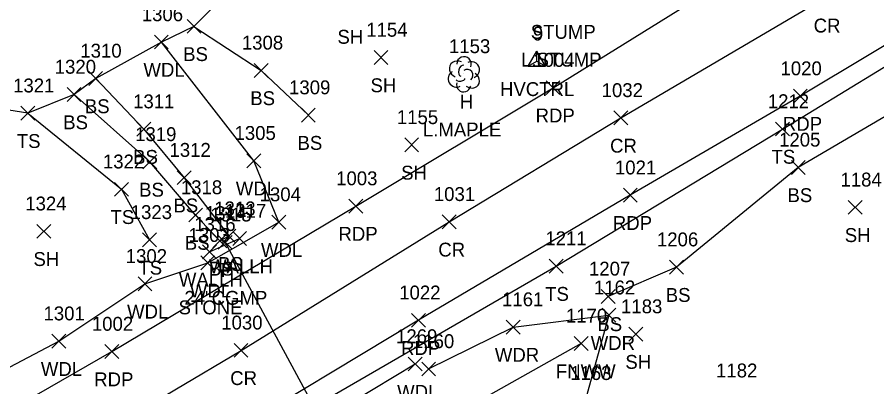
# Model space of a CAD drawing. Extents: x 1526508 to 1531550, y 369926 to 373082.
# Drawn here: x 1530712.1 to 1530836, y 370020.6 to 370073.8 of the extents above; entities that cross this region are included whole.
import ezdxf

# ---------------------------------------------------------------- set-up
doc = ezdxf.new("R2010")
doc.units = 0
for name, color, linetype in [('C_A', 7, 'Continuous'), ('C_I', 7, 'Continuous'), ('CPSM', 7, 'Continuous'), ('D_A', 7, 'Continuous'), ('D_C', 7, 'Continuous'), ('D_I', 7, 'Continuous'), ('D_TIC', 7, 'Continuous'), ('DCP', 7, 'Continuous'), ('DHW', 7, 'Continuous'), ('L_A', 7, 'Continuous'), ('L_C', 7, 'Continuous'), ('L_I', 7, 'Continuous'), ('L_TIC', 7, 'Continuous'), ('LAWA', 7, 'Continuous'), ('LELB', 7, 'Continuous'), ('LFNC', 7, 'Continuous'), ('LSOGP', 7, 'Continuous'), ('LTD', 7, 'Continuous'), ('P_A', 7, 'Continuous'), ('P_I', 7, 'Continuous'), ('P_TIC', 7, 'Continuous'), ('PET', 7, 'Continuous'), ('PRC', 7, 'Continuous')]:
    doc.layers.add(name, color=color, linetype=linetype)

msp = doc.modelspace()

# ---------------------------------------------------------------- linework, layer by layer
at = {"layer": 'CPSM'}
for p, q in [((1530785.76, 370066.72), (1530787.01, 370068.89)), ((1530788.26, 370066.72), (1530787.01, 370068.89)), ((1530787.01, 370067.44), (1530787.01, 370068.89)), ((1530785.76, 370066.72), (1530787.01, 370067.44)), ((1530787.01, 370067.44), (1530787.01, 370067.44)), ((1530787.01, 370067.44), (1530788.26, 370066.72)), ((1530785.76, 370066.72), (1530788.26, 370066.72))]:
    msp.add_line(p, q, dxfattribs=at)
at = {"layer": 'D_TIC'}
for points in [[(1530741.1, 370040.37), (1530743.1, 370042.37)], [(1530743.1, 370040.37), (1530741.1, 370042.37)], [(1530743.2, 370040.91), (1530745.2, 370042.91)], [(1530745.2, 370040.91), (1530743.2, 370042.91)], [(1530738.85, 370039), (1530740.85, 370041)], [(1530740.85, 370039), (1530738.85, 370041)]]:
    msp.add_lwpolyline(points, dxfattribs=at)
at = {"layer": 'DCP'}
msp.add_lwpolyline([(1530757.89, 370012.13), (1530742.1, 370041.37)], dxfattribs=at)
at = {"layer": 'DHW'}
msp.add_lwpolyline([(1530739.85, 370040), (1530744.2, 370041.91)], dxfattribs=at)
at = {"layer": 'L_TIC'}
for points in [[(1530736.62, 370071.48), (1530738.62, 370073.48)], [(1530738.62, 370071.48), (1530736.62, 370073.48)], [(1530731.92, 370069.22), (1530733.92, 370071.22)], [(1530733.92, 370069.22), (1530731.92, 370071.22)], [(1530763.57, 370066.99), (1530765.57, 370068.99)], [(1530765.57, 370066.99), (1530763.57, 370068.99)], [(1530746.29, 370065.13), (1530748.29, 370067.13)], [(1530748.29, 370065.13), (1530746.29, 370067.13)], [(1530722.46, 370063.97), (1530724.46, 370065.97)], [(1530724.46, 370063.97), (1530722.46, 370065.97)], [(1530719.34, 370061.66), (1530721.34, 370063.66)], [(1530721.34, 370061.66), (1530719.34, 370063.66)], [(1530712.68, 370058.96), (1530714.68, 370060.96)], [(1530714.68, 370058.96), (1530712.68, 370060.96)], [(1530753.1, 370058.69), (1530755.1, 370060.69)], [(1530755.1, 370058.69), (1530753.1, 370060.69)], [(1530729.41, 370056.67), (1530731.41, 370058.67)], [(1530731.41, 370056.67), (1530729.41, 370058.67)], [(1530821.42, 370056.69), (1530823.42, 370058.69)], [(1530823.42, 370056.69), (1530821.42, 370058.69)], [(1530767.98, 370054.4), (1530769.98, 370056.4)], [(1530769.98, 370054.4), (1530767.98, 370056.4)], [(1530730.27, 370051.95), (1530732.27, 370053.95)], [(1530732.27, 370051.95), (1530730.27, 370053.95)], [(1530745.24, 370052.12), (1530747.24, 370054.12)], [(1530747.24, 370052.12), (1530745.24, 370054.12)], [(1530823.69, 370051.16), (1530825.69, 370053.16)], [(1530825.69, 370051.16), (1530823.69, 370053.16)], [(1530735.22, 370049.68), (1530737.22, 370051.68)], [(1530737.22, 370049.68), (1530735.22, 370051.68)], [(1530726.19, 370048.01), (1530728.19, 370050.01)], [(1530728.19, 370048.01), (1530726.19, 370050.01)], [(1530831.89, 370045.41), (1530833.89, 370047.41)], [(1530833.89, 370045.41), (1530831.89, 370047.41)], [(1530736.86, 370044.3), (1530738.86, 370046.3)], [(1530738.86, 370044.3), (1530736.86, 370046.3)], [(1530748.85, 370043.28), (1530750.85, 370045.28)], [(1530750.85, 370043.28), (1530748.85, 370045.28)], [(1530715, 370041.96), (1530717, 370043.96)], [(1530717, 370041.96), (1530715, 370043.96)], [(1530730.2, 370040.72), (1530732.2, 370042.72)], [(1530732.2, 370040.72), (1530730.2, 370042.72)], [(1530740.33, 370040.58), (1530742.33, 370042.58)], [(1530742.33, 370040.58), (1530740.33, 370042.58)], [(1530741.67, 370041.25), (1530743.67, 370043.25)], [(1530743.67, 370041.25), (1530741.67, 370043.25)], [(1530738.6, 370037.43), (1530740.6, 370039.43)], [(1530740.6, 370037.43), (1530738.6, 370039.43)], [(1530788.81, 370036.94), (1530790.81, 370038.94)], [(1530790.81, 370036.94), (1530788.81, 370038.94)], [(1530806.15, 370036.79), (1530808.15, 370038.79)], [(1530808.15, 370036.79), (1530806.15, 370038.79)], [(1530729.56, 370034.39), (1530731.56, 370036.39)], [(1530731.56, 370034.39), (1530729.56, 370036.39)], [(1530796.3, 370032.58), (1530798.3, 370034.58)], [(1530798.3, 370032.58), (1530796.3, 370034.58)], [(1530796.41, 370029.87), (1530798.41, 370031.87)], [(1530798.41, 370029.87), (1530796.41, 370031.87)], [(1530782.61, 370028.16), (1530784.61, 370030.16)], [(1530784.61, 370028.16), (1530782.61, 370030.16)], [(1530800.28, 370027.15), (1530802.28, 370029.15)], [(1530802.28, 370027.15), (1530800.28, 370029.15)], [(1530717.14, 370026.13), (1530719.14, 370028.13)], [(1530719.14, 370026.13), (1530717.14, 370028.13)], [(1530792.41, 370025.8), (1530794.41, 370027.8)], [(1530794.41, 370025.8), (1530792.41, 370027.8)], [(1530768.48, 370022.84), (1530770.48, 370024.84)], [(1530770.48, 370022.84), (1530768.48, 370024.84)], [(1530770.43, 370022.13), (1530772.43, 370024.13)], [(1530772.43, 370022.13), (1530770.43, 370024.13)]]:
    msp.add_lwpolyline(points, dxfattribs=at)
at = {"layer": 'LAWA'}
for points in [[(1530657.29, 369993.12), (1530673.96, 370004), (1530696.13, 370015.56), (1530718.14, 370027.13), (1530730.56, 370035.39), (1530739.6, 370038.43), (1530749.85, 370044.28), (1530746.24, 370053.12), (1530732.92, 370070.22)], [(1530771.43, 370023.13), (1530783.61, 370029.16), (1530797.41, 370030.87), (1530793.99, 370018.54), (1530795.33, 370003.35), (1530805.3, 370002.27)], [(1530769.48, 370023.84), (1530754.36, 370014.7), (1530742.13, 370006.46), (1530732.58, 369998.98), (1530723.17, 369990.78), (1530701.39, 369977.34), (1530688.96, 369968.61), (1530674.75, 369962.19)]]:
    msp.add_lwpolyline(points, dxfattribs=at)
at = {"layer": 'LELB'}
for points in [[(1530685.88, 369975.28), (1530717.44, 369995.35), (1530750.55, 370015.24), (1530789.81, 370037.94), (1530822.42, 370057.69), (1530849.78, 370074.39), (1530878.97, 370089.95), (1530906.44, 370104.85), (1530934.55, 370113.45), (1530953.41, 370116.76)], [(1530737.62, 370072.48), (1530747.29, 370066.13), (1530754.1, 370059.69)], [(1530723.46, 370064.97), (1530730.41, 370057.67), (1530736.22, 370050.68), (1530742.67, 370042.25), (1530741.33, 370041.58), (1530737.86, 370045.3), (1530731.27, 370052.95), (1530720.34, 370062.66)], [(1530844.42, 370063.73), (1530824.69, 370052.16), (1530807.15, 370037.79), (1530797.3, 370033.58)], [(1530713.68, 370059.96), (1530727.19, 370049.01), (1530731.2, 370041.72)]]:
    msp.add_lwpolyline(points, dxfattribs=at)
at = {"layer": 'LFNC'}
msp.add_lwpolyline([(1530793.41, 370026.8), (1530770.35, 370013.82)], dxfattribs=at)
at = {"layer": 'LSOGP'}
msp.add_lwpolyline([(1530751.36, 370086.4), (1530737.62, 370072.48), (1530732.92, 370070.22), (1530723.46, 370064.97), (1530720.34, 370062.66), (1530713.68, 370059.96), (1530700.23, 370062.11)], dxfattribs=at)
at = {"layer": 'LTD'}
msp.add_line((1530776.49, 370065.62), (1530776.49, 370065.62), dxfattribs=at)
msp.add_line((1530776.49, 370065.62), (1530776.49, 370065.62), dxfattribs=at)
msp.add_arc((1530776.53, 370067.06), 1.05, 335.5272, 180.9563, dxfattribs=at)
for centre, major_axis, ratio, start_param, end_param in [((1530775.7, 370066.29), (1.21, -0.51), 0.895232, 1.570796, 4.712389), ((1530777.53, 370066.21), (-1.14, -0.48), 0.949671, 1.570796, 4.712389), ((1530775.4, 370064.91), (0.58, -1.04), 0.959034, 3.141593, 6.283185), ((1530776.28, 370066.08), (-0.208, -0.792), 0.645439, 3.141593, 6.283185), ((1530776.99, 370065.46), (-0.5, 0.667), 0.989748, 3.141593, 6.283185), ((1530776.03, 370064.87), (-0.625, -0.083), 0.423636, 0, 3.141593), ((1530777.49, 370064.79), (-1.09, 0.79), 0.841452, 1.570796, 4.712389), ((1530776.49, 370064.12), (0.26, 1.06), 0.942809, 1.570796, 4.712389)]:
    msp.add_ellipse(centre, major_axis=major_axis, ratio=ratio, start_param=start_param, end_param=end_param, dxfattribs=at)
at = {"layer": 'P_TIC'}
for points in [[(1530788.35, 370062.64), (1530790.35, 370064.64)], [(1530790.35, 370062.64), (1530788.35, 370064.64)], [(1530823.98, 370061.43), (1530825.98, 370063.43)], [(1530825.98, 370061.43), (1530823.98, 370063.43)], [(1530798.13, 370058.29), (1530800.13, 370060.29)], [(1530800.13, 370058.29), (1530798.13, 370060.29)], [(1530799.48, 370047.15), (1530801.48, 370049.15)], [(1530801.48, 370047.15), (1530799.48, 370049.15)], [(1530759.95, 370045.59), (1530761.95, 370047.59)], [(1530761.95, 370045.59), (1530759.95, 370047.59)], [(1530773.39, 370043.32), (1530775.39, 370045.32)], [(1530775.39, 370043.32), (1530773.39, 370045.32)], [(1530768.96, 370029.14), (1530770.96, 370031.14)], [(1530770.96, 370029.14), (1530768.96, 370031.14)], [(1530724.77, 370024.63), (1530726.77, 370026.63)], [(1530726.77, 370024.63), (1530724.77, 370026.63)], [(1530743.4, 370024.81), (1530745.4, 370026.81)], [(1530745.4, 370024.81), (1530743.4, 370026.81)]]:
    msp.add_lwpolyline(points, dxfattribs=at)
at = {"layer": 'PET'}
for points in [[(1530659.86, 369987.59), (1530689.68, 370004.88), (1530725.77, 370025.63), (1530760.95, 370046.59), (1530789.35, 370063.64), (1530821.52, 370083.59), (1530847.47, 370098.66), (1530877.57, 370115.25), (1530907.84, 370128.26), (1530938.81, 370136.76), (1530967.77, 370140.97), (1531005.44, 370146.08), (1531034.99, 370150.93)], [(1531038.44, 370130.38), (1531006.6, 370125.67), (1530965.47, 370120.56), (1530935.63, 370115.81), (1530906.91, 370106.24), (1530877.46, 370092.89), (1530855.5, 370080.74), (1530824.98, 370062.43), (1530800.48, 370048.15), (1530769.96, 370030.14), (1530741.1, 370012.79), (1530710.76, 369994.53), (1530684.03, 369978.66), (1530669.6, 369970.09)]]:
    msp.add_lwpolyline(points, dxfattribs=at)
at = {"layer": 'PRC'}
msp.add_lwpolyline([(1530664.43, 369978.53), (1530688.65, 369992.9), (1530715.76, 370008.79), (1530744.4, 370025.81), (1530774.39, 370044.32), (1530799.13, 370059.29), (1530828.47, 370076.59), (1530863.72, 370096.73), (1530899.64, 370113.89), (1530935.78, 370125.96), (1530974.77, 370132.27), (1531009.67, 370136.56), (1531036.22, 370140.48)], dxfattribs=at)

# ---------------------------------------------------------------- texts
at = {"layer": 'C_A'}
msp.add_text('HVCTRL', height=2, dxfattribs=at).set_placement((1530781.71, 370062.44))
at = {"layer": 'C_I'}
msp.add_text('9', height=2, dxfattribs=at).set_placement((1530786.44, 370070.44))
at = {"layer": 'D_A'}
for s, p in [('WALLH', (1530739.79, 370036.91)), ('P', (1530741.48, 370036.37)), ('WALLH', (1530735.44, 370035))]:
    msp.add_text(s, height=2, dxfattribs=at).set_placement(p)
at = {"layer": 'D_C'}
for s, p in [('24"CGMP', (1530736.24, 370032.37)), ('STONE', (1530735.4, 370031))]:
    msp.add_text(s, height=2, dxfattribs=at).set_placement(p)
at = {"layer": 'D_I'}
for s, p in [('1315', (1530739.98, 370044.37)), ('1317', (1530742.08, 370044.91)), ('1316', (1530737.67, 370043))]:
    msp.add_text(s, height=2, dxfattribs=at).set_placement(p)
at = {"layer": 'L_A'}
for s, p in [('STUMP', (1530786.14, 370070.68)), ('SH', (1530758.29, 370069.97)), ('BS', (1530736.06, 370067.48)), ('WDL', (1530730.34, 370065.22)), ('SH', (1530763.06, 370062.99)), ('BS', (1530745.73, 370061.13)), ('H', (1530775.92, 370060.62)), ('BS', (1530721.9, 370059.97)), ('BS', (1530718.78, 370057.66)), ('TS', (1530712.09, 370054.96)), ('BS', (1530752.54, 370054.69)), ('BS', (1530728.85, 370052.67)), ('TS', (1530820.83, 370052.69)), ('SH', (1530767.47, 370050.4)), ('BS', (1530729.72, 370047.95)), ('WDL', (1530743.65, 370048.12)), ('BS', (1530823.13, 370047.16)), ('BS', (1530734.66, 370045.68)), ('TS', (1530725.6, 370044.01)), ('BS', (1530736.3, 370040.3)), ('SH', (1530831.38, 370041.41)), ('WDL', (1530747.27, 370039.28)), ('SH', (1530714.49, 370037.96)), ('TS', (1530729.61, 370036.72)), ('BS', (1530739.77, 370036.58)), ('BS', (1530741.11, 370037.25)), ('WDL', (1530737.02, 370033.43)), ('TS', (1530788.22, 370032.94)), ('BS', (1530805.59, 370032.79)), ('WDL', (1530727.98, 370030.39)), ('BS', (1530795.74, 370028.58)), ('WDR', (1530794.78, 370025.87)), ('WDR', (1530780.97, 370024.16)), ('SH', (1530799.77, 370023.15)), ('WDL', (1530715.56, 370022.13)), ('FNWW', (1530789.76, 370021.8)), ('WDL', (1530766.89, 370018.84))]:
    msp.add_text(s, height=2, dxfattribs=at).set_placement(p)
at = {"layer": 'L_C'}
for s, p in [('L.STUMP', (1530784.75, 370066.68)), ('L.MAPLE', (1530770.6, 370056.62))]:
    msp.add_text(s, height=2, dxfattribs=at).set_placement(p)
at = {"layer": 'L_I'}
for s, p in [('1306', (1530730.1, 370073.22)), ('1154', (1530762.44, 370070.99)), ('1308', (1530744.52, 370069.13)), ('1310', (1530721.25, 370067.97)), ('1153', (1530774.36, 370068.62)), ('1320', (1530717.56, 370065.66)), ('1321', (1530711.56, 370062.96)), ('1309', (1530751.32, 370062.69)), ('1311', (1530728.85, 370060.67)), ('1212', (1530820.29, 370060.69)), ('1155', (1530766.85, 370058.4)), ('1319', (1530729.14, 370055.95)), ('1305', (1530743.46, 370056.12)), ('1205', (1530821.92, 370055.16)), ('1312', (1530734.09, 370053.68)), ('1322', (1530724.5, 370052.01)), ('1184', (1530830.76, 370049.41)), ('1318', (1530735.73, 370048.3)), ('1304', (1530747.08, 370047.28)), ('1324', (1530713.31, 370045.96)), ('1313', (1530740.54, 370045.25)), ('1323', (1530728.51, 370044.72)), ('1314', (1530739.2, 370044.58)), ('1303', (1530736.83, 370041.43)), ('1211', (1530788.25, 370040.94)), ('1206', (1530804.32, 370040.79)), ('1302', (1530727.79, 370038.39)), ('1207', (1530794.53, 370036.58)), ('1162', (1530795.24, 370033.87)), ('1161', (1530782.01, 370032.16)), ('1183', (1530799.15, 370031.15)), ('1301', (1530715.94, 370030.13)), ('1170', (1530791.2, 370029.8)), ('1269', (1530766.73, 370026.84)), ('1160', (1530769.17, 370026.13)), ('1182', (1530812.84, 370021.91)), ('1163', (1530791.82, 370021.54))]:
    msp.add_text(s, height=2, dxfattribs=at).set_placement(p)
at = {"layer": 'P_A'}
for s, p in [('CR', (1530826.9, 370071.59)), ('RDP', (1530786.84, 370058.64)), ('RDP', (1530822.47, 370057.43)), ('CR', (1530797.57, 370054.29)), ('RDP', (1530797.97, 370043.15)), ('RDP', (1530758.44, 370041.59)), ('CR', (1530772.82, 370039.32)), ('RDP', (1530767.45, 370025.14)), ('RDP', (1530723.25, 370020.63)), ('CR', (1530742.84, 370020.81))]:
    msp.add_text(s, height=2, dxfattribs=at).set_placement(p)
at = {"layer": 'P_I'}
for s, p in [('1004', (1530786.5, 370066.64)), ('1020', (1530822.12, 370065.43)), ('1032', (1530796.36, 370062.29)), ('1021', (1530798.27, 370051.15)), ('1003', (1530758.1, 370049.59)), ('1031', (1530772.18, 370047.32)), ('1022', (1530767.19, 370033.14)), ('1002', (1530722.91, 370028.63)), ('1030', (1530741.55, 370028.81))]:
    msp.add_text(s, height=2, dxfattribs=at).set_placement(p)

doc.saveas('drawing.dxf')
